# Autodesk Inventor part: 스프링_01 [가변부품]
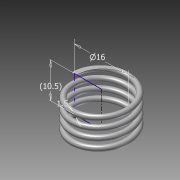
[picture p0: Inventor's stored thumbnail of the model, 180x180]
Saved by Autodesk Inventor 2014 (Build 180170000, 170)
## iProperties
Created: 2015-07
Part Number: 스프링_01 [가변부품]
Material: 강철, 연강
Document SubType Name: Modeling
Designer: Administrator
Density: 7.86 g/cm^3
Appearance: 강철
Mass: 2.7115 g
Surface Area: 9.40476 cm^2
Volume: 0.344974 cm^3
Author: Administrator
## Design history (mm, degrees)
sketch "스케치1"
  geometry: L1 (0, 0)-(8, 0); L2 (8, 0)-(8, 10.5); L3 (8, 10.5)-(0, 10.5); L4 (0, 10.5)-(0, 0); C1 r 0.75 at (8, 0)
  constraints: 8 end point, 2 parallel, 1 centre point, 1 coincident, 1 horizontal, 1 perpendicular
  dimensions: "d0" = 16 diameter of L2 L4; "d1" = 10.5 distance between parallel lines of L1 L3 (derived); "d2" = 1.5 diameter of C1
feature "코일1" sketch "스케치1" pitch "d3" = 10; turns "d5" = 4; dims "d4" = 10.5 (= d1), "d6" = 0, angle "d7" = 90 deg, angle "d8" = 90 deg, "d9" = 0, "d10" = 0
sketch "스케치2"
  geometry: L1 (-8.75, 0)-(-7.25, 0) reference; 1 further point
  constraints: 1 horizontal alignment
extrude "돌출1" cut sketch "스케치2" stored distance "d11" = 10; taper "d12" = 0 deg
node "작업 평면1"
sketch "스케치3"
  geometry: L1 (0.75, 0)-(-0.75, 0) reference; 1 further point
  constraints: 1 horizontal alignment
extrude "돌출2" cut sketch "스케치3" stored distance "d13" = 10; taper "d14" = 0 deg
node "솔리드1"
node "절단 모서리 투영1"
node "절단 모서리 투영2"
